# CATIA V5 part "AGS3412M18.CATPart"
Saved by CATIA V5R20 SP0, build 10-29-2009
Part number: AGS3412M18
Definition: NONE
Nomenclature: AGS3412M18
Source: Unknown
Description: AGS3412M18
Bounding box of the stored display mesh (mm): x -33 to 35, y -32.5 to 32.5, z -32.5 to 32.5
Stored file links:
  C:\Users\Utente\Desktop\IO LAVORO\3D X SITO CF\X SITO\PLASTICA\AGS\AGS3412M18.CATPart
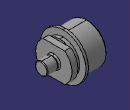
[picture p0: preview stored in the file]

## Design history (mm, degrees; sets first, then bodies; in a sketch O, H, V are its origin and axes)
Body1 "AGS3412M18" (main body)
  Solid1: solid without history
